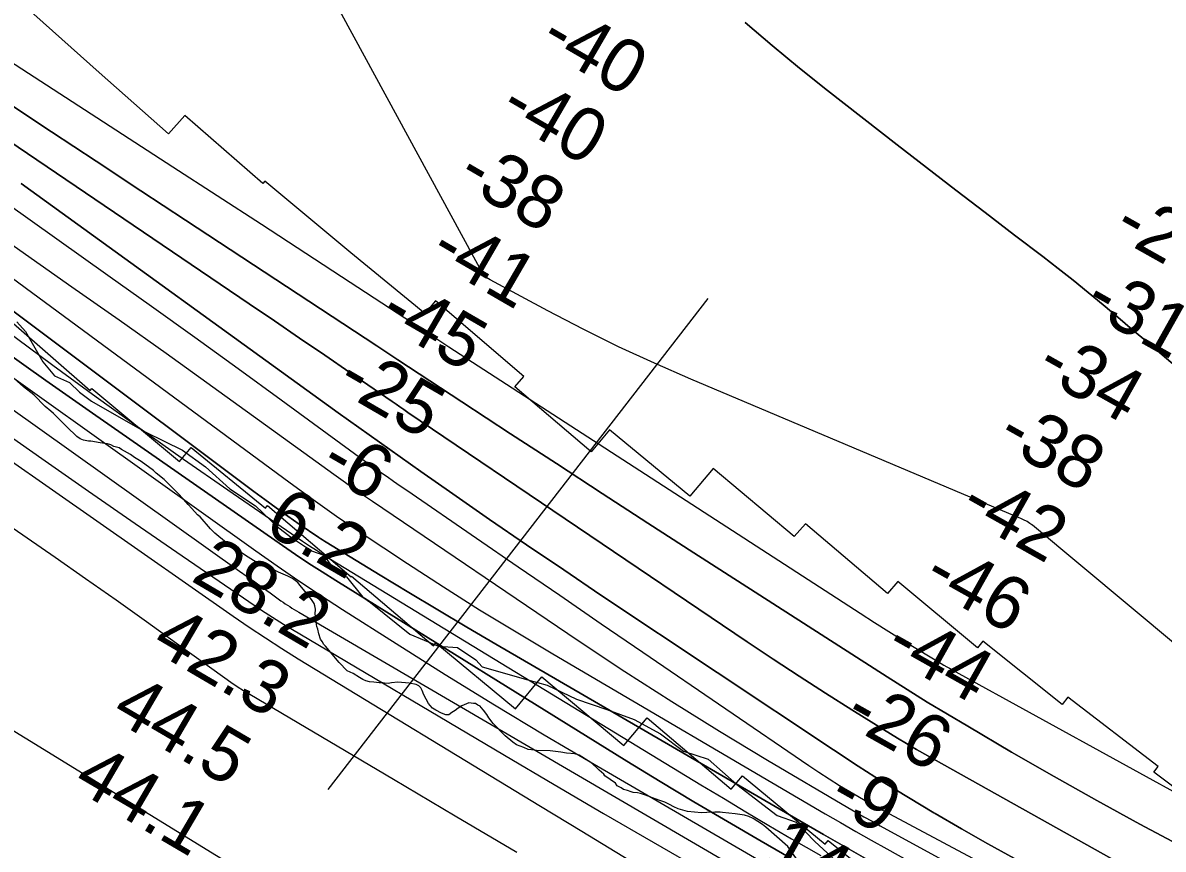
# Model space of a CAD drawing. Extents: x 3187622 to 3225504, y 800805 to 826213.
# Drawn here: x 3203820 to 3205252, y 812331 to 813370 of the extents above; entities that cross this region are included whole.
import ezdxf

# ---------------------------------------------------------------- set-up
doc = ezdxf.new("R2010")
doc.units = 0
for name, color, linetype in [('V-RIVR-EDGE', 7, 'Continuous'), ('V-RIVR-RANG', 7, 'Continuous'), ('V-RRAP-RVMT', 7, 'Continuous'), ('V-SITE-VEGE', 7, 'Continuous'), ('V-TOPO-DPTH', 7, 'Continuous'), ('V-TOPO-MAJR', 7, 'Continuous'), ('V-TOPO-MINR', 7, 'Continuous'), ('V-TOPO-WATR', 7, 'Continuous')]:
    doc.layers.add(name, color=color, linetype=linetype)

msp = doc.modelspace()

# ---------------------------------------------------------------- linework, layer by layer
at = {"layer": 'V-RIVR-EDGE'}
for points in [[(3203811.9, 812994.3), (3203823.1, 812982.1), (3203844.8, 812943.8), (3203859.5, 812926.4), (3203878.2, 812918.1), (3203890.8, 812905.9), (3203906, 812894.6), (3203955, 812866.2), (3203974.1, 812855.3), (3204020.1, 812833), (3204049.2, 812812), (3204079.6, 812784.2), (3204112.1, 812762.8), (3204139, 812737.1), (3204155.9, 812724), (3204182.4, 812706.5)], [(3204182.4, 812706.5), (3204198, 812700.8), (3204211, 812682.5), (3204226.2, 812673.8), (3204247, 812648.1), (3204256.5, 812641.6), (3204306, 812601.5), (3204342, 812586.6), (3204365.9, 812584.8), (3204388.9, 812569.5), (3204396.7, 812560.4), (3204454.1, 812544.2), (3204478.4, 812537.6), (3204515.3, 812520.1), (3204553.5, 812507), (3204587.8, 812494.3), (3204620.8, 812476.4), (3204649.5, 812454.6), (3204680.7, 812444.5), (3204716.7, 812412.7), (3204767.5, 812373.9), (3204791.4, 812365.5), (3204814.8, 812341.1), (3204840.8, 812317.2)]]:
    msp.add_lwpolyline(points, dxfattribs=at)
at = {"layer": 'V-RIVR-RANG'}
msp.add_line((3204203.4, 812406.3), (3204680.5, 813023.5), dxfattribs=at)
at = {"layer": 'V-RRAP-RVMT'}
for p, q in [((3203915.5, 813307.4), (3203809.4, 813402.6)), ((3204002.8, 813230.4), (3203915.5, 813307.4)), ((3204023.1, 813253.3), (3204002.8, 813230.4)), ((3204121.1, 813168), (3204023.1, 813253.3)), ((3204123.7, 813171), (3204121.1, 813168)), ((3204231.6, 813080.9), (3204123.7, 813171)), ((3204324.7, 813004.6), (3204231.6, 813080.9)), ((3204338.1, 813020.4), (3204324.7, 813004.6)), ((3204449.1, 812925.5), (3204338.1, 813020.4)), ((3203807.8, 812992.1), (3203904.2, 812908)), ((3204438, 812912.4), (3204449.1, 812925.5)), ((3204533.7, 812830.9), (3204438, 812912.4)), ((3203904.2, 812908), (3203906.4, 812910.5)), ((3203906.4, 812910.5), (3204016.3, 812818.7)), ((3204556.8, 812858.6), (3204533.7, 812830.9)), ((3204657.7, 812775.2), (3204556.8, 812858.6)), ((3204016.3, 812818.7), (3204031.2, 812836.3)), ((3204031.2, 812836.3), (3204124.4, 812760)), ((3204687.1, 812809.8), (3204657.7, 812775.2)), ((3204788.9, 812724.3), (3204687.1, 812809.8)), ((3204124.4, 812760), (3204127.2, 812763.4)), ((3204127.2, 812763.4), (3204232, 812673.6)), ((3204802.9, 812740.4), (3204788.9, 812724.3)), ((3204906, 812652.6), (3204802.9, 812740.4)), ((3204232, 812673.6), (3204232.6, 812674.3)), ((3204232.6, 812674.3), (3204335.4, 812586.8)), ((3204918.9, 812668), (3204906, 812652.6)), ((3205019.2, 812584.6), (3204918.9, 812668)), ((3204335.4, 812586.8), (3204338.7, 812590.7)), ((3204338.7, 812590.7), (3204438.8, 812507.9)), ((3205025.8, 812592.9), (3205019.2, 812584.6)), ((3205125.5, 812513.2), (3205025.8, 812592.9)), ((3204438.8, 812507.9), (3204471.7, 812547.9)), ((3204471.7, 812547.9), (3204574.9, 812461.7)), ((3205132.6, 812522.5), (3205125.5, 812513.2)), ((3205246.1, 812435.1), (3205132.6, 812522.5)), ((3204574.9, 812461.7), (3204604, 812496.5)), ((3204604, 812496.5), (3204709.6, 812407)), ((3204709.6, 812407), (3204723.8, 812423.6)), ((3204723.8, 812423.6), (3204827.8, 812337.5)), ((3205240.7, 812428.1), (3205246.1, 812435.1)), ((3205335.5, 812356.7), (3205240.7, 812428.1)), ((3204827.8, 812337.5), (3204831.6, 812342.1)), ((3204831.6, 812342.1), (3204936.3, 812258.4))]:
    msp.add_line(p, q, dxfattribs=at)
at = {"layer": 'V-SITE-VEGE'}
for points in [[(3204246.7, 812544.7), (3204242.5, 812547.2), (3204234.6, 812552.3), (3204227.3, 812555.5), (3204217.1, 812566.1), (3204199.8, 812586.7), (3204198, 812588.5), (3204195.6, 812592.3), (3204193.8, 812595.4), (3204191.5, 812602.1), (3204190.4, 812607.7), (3204189.2, 812611.4), (3204188.6, 812613.8), (3204188.1, 812618.1), (3204188.2, 812621.2), (3204187.1, 812626.7), (3204187.2, 812632.9), (3204186.6, 812637.2), (3204185.5, 812640.3), (3204182.5, 812645.2), (3204175.9, 812653.3), (3204168.1, 812662.6), (3204165.1, 812666.4), (3204158.5, 812671.4), (3204152.4, 812674.6), (3204140.9, 812679.7), (3204127.5, 812686.1), (3204120.2, 812688.1), (3204116, 812690), (3204102.6, 812698.2), (3204079.1, 812714), (3204075.4, 812716.5), (3204060.9, 812728.5), (3204055.5, 812734.1), (3204042.3, 812749), (3204039.3, 812751.5), (3204032.1, 812759.6), (3204027.3, 812764.6), (3204021.9, 812770.9), (3204013.5, 812779.6), (3203997.3, 812795.9), (3203987, 812804), (3203984, 812807.1), (3203968.3, 812818.5), (3203959.8, 812823.5), (3203955, 812827.3), (3203943.5, 812833.7), (3203940.5, 812835.6), (3203933.8, 812837.5), (3203930.1, 812839.4), (3203925.9, 812840.7), (3203916.7, 812842.1), (3203905.1, 812844.2), (3203902, 812844.3), (3203895.9, 812845.6), (3203891.7, 812846.9), (3203887.4, 812850.1), (3203874.8, 812862), (3203858, 812878.8), (3203855, 812881.9), (3203847.7, 812887.6), (3203833.3, 812902.6), (3203820.6, 812912.6), (3203805.6, 812925.8)], [(3204796.8, 812312.3), (3204780.7, 812334.6), (3204753, 812359.1), (3204748.8, 812362.2), (3204737.3, 812369.8), (3204731.8, 812372.3), (3204726.3, 812374.3), (3204714.7, 812375.7), (3204698.8, 812377.3), (3204695.7, 812377.9), (3204689, 812378.1), (3204679.2, 812377.6), (3204672.4, 812377.2), (3204654.7, 812378.7), (3204643.1, 812382), (3204637.7, 812384.6), (3204632.2, 812387.7), (3204626.1, 812390.3), (3204618.8, 812392.9), (3204610.9, 812396.1), (3204601.8, 812399.4), (3204595.7, 812401.3), (3204592, 812402), (3204586.5, 812402.7), (3204584.1, 812403.4), (3204579.2, 812405.3), (3204574.4, 812406.6), (3204571.3, 812408.5), (3204566.5, 812411.1), (3204564.1, 812414.2), (3204550.8, 812423.6), (3204549.6, 812425.5), (3204543.6, 812430.5), (3204540.6, 812434.2), (3204536.4, 812438), (3204533.3, 812440.5), (3204518.8, 812449.4), (3204513.3, 812451.3), (3204502.9, 812452.1), (3204495.6, 812453.5), (3204482.2, 812455), (3204465, 812455.3), (3204462.6, 812456), (3204454.6, 812456.7), (3204449.1, 812459.3), (3204440, 812462.5), (3204435.2, 812465.7), (3204425.5, 812473.8), (3204410.5, 812489.5), (3204405.1, 812496.3), (3204402.8, 812500.6), (3204398.6, 812506.2), (3204395.6, 812509.4), (3204394.4, 812511.2), (3204391.3, 812512.5), (3204388.3, 812514.4), (3204385.9, 812514.4), (3204379.8, 812515.2), (3204371.1, 812511.7), (3204366.8, 812508.7), (3204363, 812505.7), (3204358.7, 812503.3), (3204355, 812500.3), (3204351.3, 812500.4), (3204345.8, 812502.3), (3204338.5, 812506.2), (3204334.3, 812508.7), (3204331.3, 812511.8), (3204329.5, 812514.3), (3204323.6, 812525.5), (3204321.2, 812531), (3204319.5, 812534.1), (3204317.1, 812536.6), (3204314, 812538.5), (3204304.9, 812539.9), (3204290.8, 812541.4), (3204282.8, 812540.3), (3204278.5, 812539.8), (3204274.2, 812539.9), (3204271.8, 812540.5), (3204267.5, 812540.6), (3204260.8, 812541.4), (3204255.3, 812541.5), (3204250.4, 812542.8), (3204246.7, 812544.7)]]:
    msp.add_lwpolyline(points, dxfattribs=at)
at = {"layer": 'V-TOPO-DPTH'}
for points in [[(3204727.1, 813370.5), (3204761, 813341.3), (3204795.5, 813312.9), (3204830.5, 813285), (3204918.1, 813216.7), (3204954.9, 813188.2), (3204991.7, 813159.7), (3205028.7, 813131.4), (3205065.7, 813103.1), (3205101.2, 813076.1), (3205120.4, 813061.3), (3205139.4, 813046.3), (3205158.2, 813030.9), (3205176.9, 813015.4), (3205195.4, 812999.8), (3205213.9, 812984.1), (3205232.5, 812968.4), (3205251, 812952.8), (3205299.5, 812911.7)], [(3205299.5, 812911.7), (3205251, 812952.8), (3205232.5, 812968.4), (3205213.9, 812984.1), (3205195.4, 812999.8), (3205176.9, 813015.4), (3205158.2, 813030.9), (3205139.4, 813046.3), (3205120.4, 813061.3), (3205101.2, 813076.1), (3205065.7, 813103.1), (3205028.7, 813131.4), (3204991.7, 813159.7), (3204954.9, 813188.2), (3204918.1, 813216.7), (3204830.5, 813285), (3204795.5, 813312.9), (3204761, 813341.3), (3204727.1, 813370.5)], [(3205331.7, 812238.8), (3204942.6, 812456.7), (3204935.2, 812461), (3204927.8, 812465.3), (3204920.5, 812469.7), (3204913.2, 812474.2), (3204861.2, 812506.6), (3204828.1, 812527.6), (3204795.1, 812548.8), (3204762.4, 812570.3), (3204729.8, 812592.1), (3204303.5, 812880.4), (3204298.5, 812883.8), (3204293.5, 812887.2), (3204288.6, 812890.6), (3204283.6, 812894), (3204230.5, 812930.5), (3204198.9, 812952.2), (3204167.3, 812973.8), (3204135.7, 812995.3), (3204104, 813016.8), (3203704.1, 813287.6)], [(3203704.1, 813287.6), (3204104, 813016.8), (3204135.7, 812995.3), (3204167.3, 812973.8), (3204198.9, 812952.2), (3204230.5, 812930.5), (3204283.6, 812894), (3204288.6, 812890.6), (3204293.5, 812887.2), (3204298.5, 812883.8), (3204303.5, 812880.4), (3204729.8, 812592.1), (3204762.4, 812570.3), (3204795.1, 812548.8), (3204828.1, 812527.6), (3204861.2, 812506.6), (3204913.2, 812474.2), (3204920.5, 812469.7), (3204927.8, 812465.3), (3204935.2, 812461), (3204942.6, 812456.7), (3205331.7, 812238.8)], [(3205277.7, 812334), (3205223.2, 812362.9), (3205169.1, 812392.4), (3205115.4, 812422.6), (3205062, 812453.4), (3205006.8, 812485.8), (3204981.3, 812500.9), (3204955.9, 812516.2), (3204930.8, 812531.9), (3204905.8, 812547.8), (3204662.8, 812704), (3204605.1, 812741.1), (3204547.5, 812778.4), (3204490, 812815.9), (3204432.5, 812853.4), (3204371.3, 812893.6), (3204344.5, 812911.1), (3204317.7, 812928.7), (3204291, 812946.3), (3204264.2, 812963.9), (3204024.2, 813121.8), (3203968, 813158.8), (3203911.7, 813195.9), (3203855.6, 813233), (3203799.4, 813270.2)], [(3203799.4, 813270.2), (3203855.6, 813233), (3203911.7, 813195.9), (3203968, 813158.8), (3204024.2, 813121.8), (3204264.2, 812963.9), (3204291, 812946.3), (3204317.7, 812928.7), (3204344.5, 812911.1), (3204371.3, 812893.6), (3204432.5, 812853.4), (3204490, 812815.9), (3204547.5, 812778.4), (3204605.1, 812741.1), (3204662.8, 812704), (3204905.8, 812547.8), (3204930.8, 812531.9), (3204955.9, 812516.2), (3204981.3, 812500.9), (3205006.8, 812485.8), (3205062, 812453.4), (3205115.4, 812422.6), (3205169.1, 812392.4), (3205223.2, 812362.9), (3205277.7, 812334)], [(3203649.1, 813201.3), (3203881.4, 813038.3), (3203940.6, 812996.6), (3203999.6, 812954.7), (3204058.4, 812912.6), (3204117.1, 812870.3), (3204210.2, 812802.9), (3204222.3, 812794.3), (3204234.4, 812785.7), (3204246.6, 812777.3), (3204258.9, 812768.9), (3204517.4, 812593.8), (3204576.1, 812554.9), (3204635.1, 812516.8), (3204694.9, 812479.7), (3204755.1, 812443.4), (3204856.1, 812383.9), (3204866.3, 812378), (3204876.4, 812372.1), (3204886.7, 812366.4), (3204896.9, 812360.7), (3205281.9, 812150.3)], [(3203649.1, 813201.3), (3203881.4, 813038.3), (3203940.6, 812996.6), (3203999.6, 812954.7), (3204058.4, 812912.6), (3204117.1, 812870.3), (3204210.2, 812802.9), (3204222.3, 812794.3), (3204234.4, 812785.7), (3204246.6, 812777.3), (3204258.9, 812768.9), (3204517.4, 812593.8), (3204576.1, 812554.9), (3204635.1, 812516.8), (3204694.9, 812479.7), (3204755.1, 812443.4), (3204856.1, 812383.9), (3204866.3, 812378), (3204876.4, 812372.1), (3204886.7, 812366.4), (3204896.9, 812360.7), (3205281.9, 812150.3)], [(3205573.3, 812050.3), (3205099.2, 812301.5), (3205065.5, 812319.6), (3205032.1, 812338), (3204998.9, 812356.9), (3204965.8, 812376.1), (3204964.1, 812377.1), (3204932.2, 812396.2), (3204900.5, 812415.7), (3204869.2, 812435.8), (3204838, 812456.2), (3204545.9, 812650.8), (3204499.2, 812682.3), (3204452.5, 812713.9), (3204406.1, 812745.8), (3204359.8, 812777.9), (3204319.7, 812806), (3204293.7, 812824.3), (3204267.6, 812842.7), (3204241.7, 812861.2), (3204215.8, 812879.9), (3203817.4, 813167.9)], [(3203817.4, 813167.9), (3204215.8, 812879.9), (3204241.7, 812861.2), (3204267.6, 812842.7), (3204293.7, 812824.3), (3204319.7, 812806), (3204359.8, 812777.9), (3204406.1, 812745.8), (3204452.5, 812713.9), (3204499.2, 812682.3), (3204545.9, 812650.8), (3204838, 812456.2), (3204869.2, 812435.8), (3204900.5, 812415.7), (3204932.2, 812396.2), (3204964.1, 812377.1), (3204965.8, 812376.1), (3204998.9, 812356.9), (3205032.1, 812338), (3205065.5, 812319.6), (3205099.2, 812301.5), (3205573.3, 812050.3)], [(3204884.4, 812316.2), (3204854.9, 812333), (3204825.4, 812350), (3204795.9, 812367.1), (3204414, 812589.2), (3204377.4, 812610.6), (3204341, 812632.2), (3204304.7, 812654), (3204268.4, 812675.9), (3204200.8, 812717.1), (3204198.5, 812718.6), (3204196.2, 812720.1), (3204193.9, 812721.6), (3204191.6, 812723.1), (3204167, 812740), (3204152.5, 812750.1), (3204138.1, 812760.3), (3204123.8, 812770.7), (3204109.7, 812781.1), (3203649.4, 813125.5)], [(3203649.4, 813125.5), (3204109.7, 812781.1), (3204123.8, 812770.7), (3204138.1, 812760.3), (3204152.5, 812750.1), (3204167, 812740), (3204191.6, 812723.1), (3204193.9, 812721.6), (3204196.2, 812720.1), (3204198.5, 812718.6), (3204200.8, 812717.1), (3204268.4, 812675.9), (3204304.7, 812654), (3204341, 812632.2), (3204377.4, 812610.6), (3204414, 812589.2), (3204795.9, 812367.1), (3204825.4, 812350), (3204854.9, 812333), (3204884.4, 812316.2)], [(3205273.7, 812040.4), (3205223.3, 812069.3), (3204845, 812284.8), (3204838.7, 812288.5), (3204832.3, 812292.1), (3204825.9, 812295.8), (3204819.6, 812299.4), (3204747.2, 812341.3), (3204704.8, 812366.1), (3204662.6, 812391.1), (3204620.6, 812416.5), (3204578.7, 812442.2), (3204212.8, 812669.1), (3204195.8, 812679.8), (3204179, 812690.6), (3204162.4, 812701.8), (3204145.9, 812713.1), (3203907.2, 812879.2), (3203848.5, 812920.4), (3203790.1, 812961.8)]]:
    msp.add_lwpolyline(points, dxfattribs=at)
at = {"layer": 'V-TOPO-MAJR'}
for points in [[(3205571.4, 812335.2), (3205088.1, 812738.6), (3205087.4, 812739.1), (3205085, 812740.8), (3205081.6, 812743), (3205080.6, 812743.5), (3205077.7, 812745), (3205074.2, 812746.6), (3205070.6, 812748.1), (3205067.6, 812749.3), (3205064.6, 812750.6), (3205061.6, 812751.8), (3205058.6, 812753.1), (3204659.1, 812922), (3204613.4, 812942), (3204568.2, 812962.9), (3204523.6, 812985), (3204479.3, 813008), (3204406.9, 813047), (3204399.4, 813051.4), (3204015.5, 813757.6)], [(3203731, 813368.5), (3204008.1, 813189.1), (3204063.9, 813152.9), (3204119.7, 813116.7), (3204175.4, 813080.4), (3204231.1, 813044), (3204329.9, 812979.3), (3204336.1, 812975.2), (3204342.4, 812971.1), (3204348.7, 812967), (3204355, 812962.9), (3204871.6, 812627.9), (3204889.5, 812616.4), (3204907.6, 812605), (3204925.7, 812593.7), (3204943.9, 812582.6), (3204973.5, 812564.7), (3204976.9, 812562.7), (3204980.4, 812560.7), (3204983.9, 812558.7), (3204987.4, 812556.7), (3205512.9, 812267.6)], [(3203785.3, 812863.2), (3203843.7, 812822.2), (3203902.2, 812781.3), (3203960.9, 812740.7), (3204019.7, 812700.2), (3204119.7, 812631.9), (3204128.7, 812625.9), (3204137.8, 812619.9), (3204147, 812614.2), (3204156.3, 812608.6), (3204425, 812449.4), (3204487.1, 812412.8), (3204549.4, 812376.3), (3204611.7, 812340.1), (3204674.2, 812304.1)]]:
    msp.add_lwpolyline(points, dxfattribs=at)
at = {"layer": 'V-TOPO-MINR'}
for points in [[(3205299.5, 812911.7), (3205251, 812952.8), (3205232.5, 812968.4), (3205213.9, 812984.1), (3205195.4, 812999.8), (3205176.9, 813015.4), (3205158.2, 813030.9), (3205139.4, 813046.3), (3205120.4, 813061.3), (3205101.2, 813076.1), (3205065.7, 813103.1), (3205028.7, 813131.4), (3204991.7, 813159.7), (3204954.9, 813188.2), (3204918.1, 813216.7), (3204830.5, 813285), (3204795.5, 813312.9), (3204761, 813341.3), (3204727.1, 813370.5)], [(3203704.1, 813287.6), (3204104, 813016.8), (3204135.7, 812995.3), (3204167.3, 812973.8), (3204198.9, 812952.2), (3204230.5, 812930.5), (3204283.6, 812894), (3204288.6, 812890.6), (3204293.5, 812887.2), (3204298.5, 812883.8), (3204303.5, 812880.4), (3204729.8, 812592.1), (3204762.4, 812570.3), (3204795.1, 812548.8), (3204828.1, 812527.6), (3204861.2, 812506.6), (3204913.2, 812474.2), (3204920.5, 812469.7), (3204927.8, 812465.3), (3204935.2, 812461), (3204942.6, 812456.7), (3205331.7, 812238.8)], [(3203799.4, 813270.2), (3203855.6, 813233), (3203911.7, 813195.9), (3203968, 813158.8), (3204024.2, 813121.8), (3204264.2, 812963.9), (3204291, 812946.3), (3204317.7, 812928.7), (3204344.5, 812911.1), (3204371.3, 812893.6), (3204432.5, 812853.4), (3204490, 812815.9), (3204547.5, 812778.4), (3204605.1, 812741.1), (3204662.8, 812704), (3204905.8, 812547.8), (3204930.8, 812531.9), (3204955.9, 812516.2), (3204981.3, 812500.9), (3205006.8, 812485.8), (3205062, 812453.4), (3205115.4, 812422.6), (3205169.1, 812392.4), (3205223.2, 812362.9), (3205277.7, 812334)], [(3203703.1, 813211.5), (3203926.6, 813052.8), (3203981.2, 813013.9), (3204035.7, 812974.8), (3204090, 812935.5), (3204144.3, 812896), (3204236.4, 812828.8), (3204244.5, 812822.9), (3204252.6, 812817), (3204260.8, 812811.2), (3204269, 812805.4), (3204277.2, 812799.6), (3204285.4, 812793.8), (3204293.6, 812788.1), (3204301.9, 812782.4), (3204389.8, 812722.2), (3204442, 812686.4), (3204494.2, 812650.6), (3204546.4, 812614.8), (3204598.7, 812579.1), (3204807, 812436.5), (3204819.8, 812428), (3204832.6, 812419.6), (3204845.7, 812411.6), (3204858.8, 812403.7), (3204881, 812390.7), (3204885.3, 812388.2), (3204887.5, 812387), (3204889.6, 812385.9), (3205549.4, 812033.5)], [(3203649.1, 813201.3), (3203881.4, 813038.3), (3203940.6, 812996.6), (3203999.6, 812954.7), (3204058.4, 812912.6), (3204117.1, 812870.3), (3204210.2, 812802.9), (3204222.3, 812794.3), (3204234.4, 812785.7), (3204246.6, 812777.3), (3204258.9, 812768.9), (3204517.4, 812593.8), (3204576.1, 812554.9), (3204635.1, 812516.8), (3204694.9, 812479.7), (3204755.1, 812443.4), (3204856.1, 812383.9), (3204866.3, 812378), (3204876.4, 812372.1), (3204886.7, 812366.4), (3204896.9, 812360.7), (3205281.9, 812150.3)], [(3203817.4, 813167.9), (3204215.8, 812879.9), (3204241.7, 812861.2), (3204267.6, 812842.7), (3204293.7, 812824.3), (3204319.7, 812806), (3204359.8, 812777.9), (3204406.1, 812745.8), (3204452.5, 812713.9), (3204499.2, 812682.3), (3204545.9, 812650.8), (3204838, 812456.2), (3204869.2, 812435.8), (3204900.5, 812415.7), (3204932.2, 812396.2), (3204964.1, 812377.1), (3204965.8, 812376.1), (3204998.9, 812356.9), (3205032.1, 812338), (3205065.5, 812319.6), (3205099.2, 812301.5), (3205573.3, 812050.3)], [(3203615.8, 813118.8), (3203857.5, 812939.7), (3203911.9, 812899.8), (3203966.6, 812860.3), (3204021.7, 812821.5), (3204077.1, 812783), (3204171.2, 812718.6), (3204179.8, 812712.7), (3204188.5, 812707), (3204197.3, 812701.4), (3204206.2, 812695.9), (3204671.4, 812412.4), (3204699.8, 812395.3), (3204728.2, 812378.2), (3204756.8, 812361.3), (3204785.4, 812344.6), (3204822.1, 812323.3)], [(3203740.7, 813097.3), (3204155.6, 812791.8), (3204184.6, 812770.8), (3204213.8, 812750.1), (3204243.3, 812729.9), (3204273, 812710), (3204303, 812690.3), (3204348.2, 812661.1), (3204393.6, 812632.4), (3204439.4, 812604.4), (3204485.6, 812576.8), (3204827.7, 812376), (3204846.9, 812364.8), (3204866.2, 812353.7), (3204885.6, 812342.7), (3204905.1, 812331.7), (3205036.1, 812258.7), (3205121, 812211.2), (3205205.8, 812163.6), (3205290.6, 812115.9)], [(3203639.9, 813043.2), (3204112.4, 812706.2), (3204139.3, 812687.3), (3204166.3, 812668.8), (3204193.7, 812650.6), (3204221.2, 812632.8), (3204288.7, 812589.7), (3204350.4, 812551), (3204412.4, 812512.7), (3204474.8, 812475.2), (3204537.6, 812438.2), (3204790.1, 812291.3), (3204805.9, 812282.1), (3204821.7, 812272.9), (3204837.6, 812263.8), (3204853.4, 812254.7), (3205007, 812166.3), (3205091.6, 812117.4), (3205176, 812068.4), (3205260.3, 812019.1)], [(3203589.8, 813038.4), (3204091.9, 812680.8), (3204101.5, 812674), (3204111, 812667.2), (3204120.6, 812660.3), (3204130.2, 812653.5), (3204143.9, 812643.7), (3204146.7, 812641.8), (3204149.4, 812639.9), (3204152.2, 812638), (3204155, 812636.2), (3204157.8, 812634.4), (3204160.6, 812632.6), (3204163.5, 812630.9), (3204166.4, 812629.2), (3204759.4, 812282.9)], [(3203790.1, 812961.8), (3203848.5, 812920.4), (3203907.2, 812879.2), (3204145.9, 812713.1), (3204162.4, 812701.8), (3204179, 812690.6), (3204195.8, 812679.8), (3204212.8, 812669.1), (3204578.7, 812442.2), (3204620.6, 812416.5), (3204662.6, 812391.1), (3204704.8, 812366.1), (3204747.2, 812341.3), (3204819.6, 812299.4), (3204825.9, 812295.8), (3204832.3, 812292.1), (3204838.7, 812288.5), (3204845, 812284.8), (3205223.3, 812069.3), (3205273.7, 812040.4)], [(3203501.3, 812946), (3203860.1, 812698.2), (3203898.5, 812671.5), (3203936.8, 812644.6), (3203974.9, 812617.6), (3204012.9, 812590.3), (3204073.3, 812546.7), (3204081.1, 812541.3), (3204088.9, 812536), (3204096.9, 812530.9), (3204105, 812526), (3204285.3, 812419.4), (3204362.9, 812373.5), (3204440.4, 812327.5)], [(3203741.1, 812863.8), (3204083.9, 812624.2), (3204104, 812610.4), (3204124.4, 812596.8), (3204144.9, 812583.6), (3204165.7, 812570.7), (3204470.1, 812385.4), (3204521.8, 812354), (3204573.4, 812322.7), (3204625.2, 812291.6), (3204677, 812260.6), (3204713.3, 812238.9), (3204746.9, 812218.6), (3204780.5, 812198.2), (3204813.9, 812177.6), (3204847.2, 812156.8), (3204957, 812087.9), (3205041.5, 812035.1), (3205126.2, 811982.6), (3205211.2, 811930.5), (3205296.4, 811878.8)], [(3205358.5, 811593.6), (3204814.2, 811881.9), (3204787.3, 811896.1), (3204760.5, 811910.3), (3204733.6, 811924.5), (3204706.7, 811938.7), (3204665.5, 811960.5), (3204659.2, 811963.7), (3204652.9, 811966.8), (3204646.5, 811969.7), (3204640, 811972.6), (3204616.5, 811982.5), (3203425, 812715.1)]]:
    msp.add_lwpolyline(points, dxfattribs=at)
at = {"layer": 'V-TOPO-WATR'}
msp.add_lwpolyline([(3203649.4, 813125.5), (3204109.7, 812781.1), (3204123.8, 812770.7), (3204138.1, 812760.3), (3204152.5, 812750.1), (3204167, 812740), (3204191.6, 812723.1), (3204193.9, 812721.6), (3204196.2, 812720.1), (3204198.5, 812718.6), (3204200.8, 812717.1), (3204268.4, 812675.9), (3204304.7, 812654), (3204341, 812632.2), (3204377.4, 812610.6), (3204414, 812589.2), (3204795.9, 812367.1), (3204825.4, 812350), (3204854.9, 812333), (3204884.4, 812316.2)], dxfattribs=at)

# ---------------------------------------------------------------- texts
at = {"layer": 'V-RIVR-RANG'}
for s, rotation, p in [('-40', 329.8745, (3204466, 813340.3)), ('-40', 329.8745, (3204415.7, 813253.9)), ('-38', 329.8745, (3204362.4, 813169.3)), ('-29', 330.6641, (3205186.8, 813103.6)), ('-41', 329.8745, (3204327.8, 813073.7)), ('-31', 330.6641, (3205150, 813009.6)), ('-45', 329.8745, (3204264, 812995.1)), ('-34', 330.6641, (3205089.7, 812928.7)), ('-25', 329.8745, (3204210.9, 812910.3)), ('-38', 330.6641, (3205040.7, 812841.6)), ('-6', 329.8745, (3204189.8, 812807)), ('6.2', 329.8745, (3204120.3, 812731.7)), ('-42', 330.6641, (3204993.8, 812753.2)), ('28.2', 329.6283, (3204029.2, 812669.5)), ('-46', 330.6641, (3204947.8, 812664.4)), ('42.3', 329.6283, (3203978.9, 812583.1)), ('-44', 330.6641, (3204899.8, 812576.7)), ('44.5', 329.6283, (3203928.5, 812496.7)), ('-26', 330.6641, (3204848.5, 812490.8)), ('44.1', 329.6283, (3203880.2, 812409.1)), ('-9', 330.6641, (3204828.5, 812387.3)), ('14.5', 330.6641, (3204748.2, 812317.7))]:
    msp.add_text(s, height=67, rotation=rotation, dxfattribs=at).set_placement(p)

doc.saveas('drawing.dxf')
